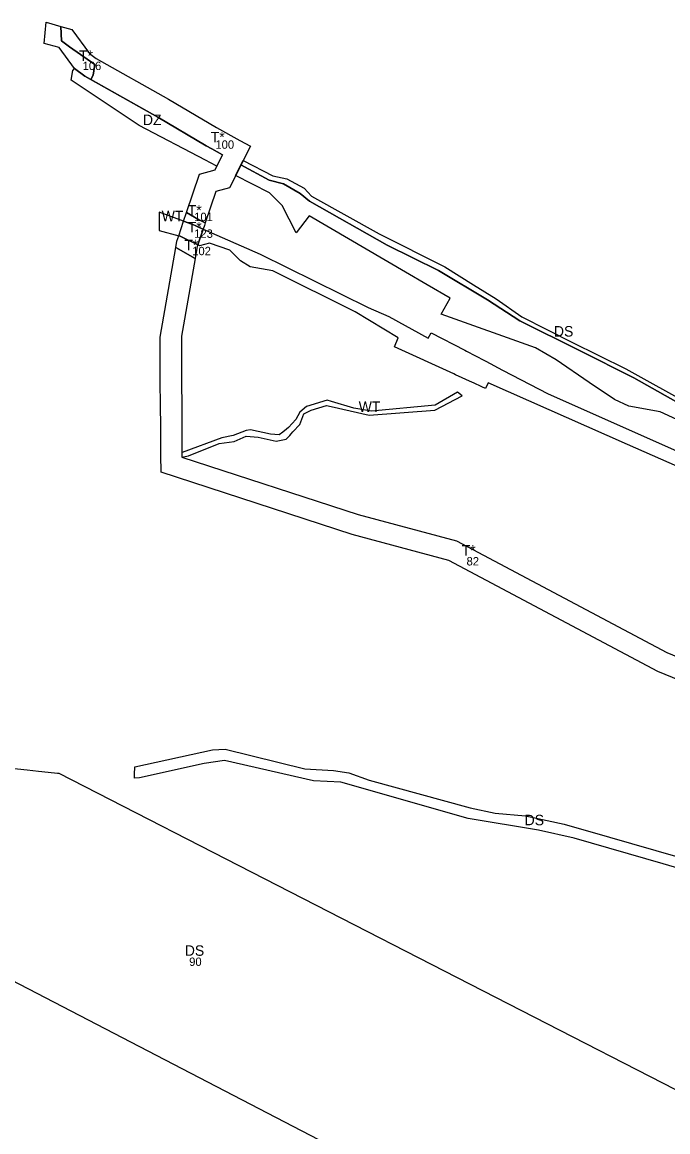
# Model space of a CAD drawing. Extents: x -521621 to -516769, y -1190068 to -1185078.
# Drawn here: x -520820 to -520203, y -1187500 to -1186440 of the extents above; entities that cross this region are included whole.
import ezdxf

# ---------------------------------------------------------------- set-up
doc = ezdxf.new("R2010")
doc.units = 0
for name, color, linetype in [('fpl_id', 7, 'Continuous'), ('v_infrastr_n', 7, 'Continuous'), ('v_infrastr_s', 7, 'Continuous'), ('voda_s', 7, 'Continuous')]:
    doc.layers.add(name, color=color, linetype=linetype)

msp = doc.modelspace()

# ---------------------------------------------------------------- linework, layer by layer
at = {"layer": 'v_infrastr_n'}
for points in [[(-520797.2, -1186439.6), (-520783, -1186443.6), (-520782.5, -1186457.5), (-520774.7, -1186463.1), (-520750.6, -1186480.1), (-520752.2, -1186490.3), (-520754.3, -1186494.4), (-520760.1, -1186491.2), (-520770, -1186483.8), (-520784.7, -1186463.9), (-520799.1, -1186459.9)], [(-520749.2, -1186474.3), (-520680.3, -1186513), (-520634.4, -1186540.3), (-520611.9, -1186552.6), (-520601.9, -1186558), (-520621.9, -1186597.7), (-520634.9, -1186601.2), (-520645.1, -1186631.2), (-520649.5, -1186629.2), (-520655.4, -1186625.8), (-520662.9, -1186621.4), (-520650.4, -1186584.7), (-520635.7, -1186580.7), (-520628.5, -1186566.3), (-520638.9, -1186560.6), (-520644.3, -1186557.7), (-520690.3, -1186530.3), (-520754.3, -1186494.4), (-520752.2, -1186490.3), (-520750.6, -1186480.1), (-520774.7, -1186463.1), (-520782.5, -1186457.5), (-520783, -1186443.6), (-520772.7, -1186446.5), (-520755.7, -1186469.5)], [(-520665.7, -1186629.7), (-520662.9, -1186621.4), (-520655.4, -1186625.8), (-520652.7, -1186627.4), (-520649.5, -1186629.2), (-520645.1, -1186631.2), (-520645.9, -1186633.8), (-520647.1, -1186637.2), (-520651.4, -1186635.3), (-520654.8, -1186633.8), (-520657.7, -1186632.5)], [(-520665.7, -1186629.7), (-520657.7, -1186632.5), (-520654.8, -1186633.8), (-520651.4, -1186635.3), (-520647.1, -1186637.2), (-520652.2, -1186652.3), (-520669.1, -1186644.1), (-520670.4, -1186643.7)], [(-520670.4, -1186643.7), (-520669.1, -1186644.1), (-520652.2, -1186652.3), (-520652.7, -1186653.6), (-520654.8, -1186665.4), (-520673.2, -1186654.8), (-520672.1, -1186648.7)]]:
    msp.add_lwpolyline(points, close=True, dxfattribs=at)
for points in [[(-520140.9, -1187089.3), (-520212.4, -1187059.9), (-520412.3, -1186953.8), (-520504.6, -1186929.1), (-520687.3, -1186869.5), (-520687.4, -1186853.1), (-520687.5, -1186835.5), (-520687.6, -1186830.6), (-520687.6, -1186824.5), (-520687.8, -1186807), (-520688, -1186781.6), (-520688.2, -1186740.5), (-520673.2, -1186654.8), (-520654.8, -1186665.4), (-520667.8, -1186739.5), (-520667.4, -1186850.6), (-520667.4, -1186855), (-520498.9, -1186909.9), (-520405, -1186935.1), (-520203.8, -1187041.8), (-520133.6, -1187070.6)], [(-520849, -1187150.2), (-520815.2, -1187153.9), (-520804.3, -1187155.1), (-520795.3, -1187156), (-520786.2, -1187157), (-520784.9, -1187157.2), (-520159, -1187477.9), (-520132.3, -1187491.8), (-520130, -1187493), (-520122.9, -1187496.1), (-520003.6, -1187488.8), (-519999.4, -1187501.1), (-519986.8, -1187542.4), (-519985.9, -1187549.9), (-519983.1, -1187579.6), (-519979.3, -1187615.3), (-519966.4, -1187650.5), (-519963.3, -1187659), (-520250.8, -1187655.6), (-520830.3, -1187354.9)]]:
    msp.add_lwpolyline(points, dxfattribs=at)
at = {"layer": 'v_infrastr_s'}
for points in [[(-520773.1, -1186494.9), (-520771.7, -1186485.7)], [(-520771.7, -1186485.7), (-520770, -1186483.8)], [(-520770, -1186483.8), (-520760.1, -1186491.2)], [(-520708.1, -1186538.4), (-520773.1, -1186494.9)], [(-520760.1, -1186491.2), (-520690.3, -1186530.3)], [(-520690.3, -1186530.3), (-520644.3, -1186557.7)], [(-520644.8, -1186571.5), (-520708.1, -1186538.4)], [(-520638.9, -1186560.6), (-520628.5, -1186566.3), (-520633.9, -1186577.1), (-520639.9, -1186574), (-520644.8, -1186571.5)], [(-520644.3, -1186557.7), (-520638.9, -1186560.6)], [(-520610.9, -1186575.9), (-520608.8, -1186571.6)], [(-520608.8, -1186571.6), (-520580.6, -1186586.5), (-520567, -1186589.1), (-520550.6, -1186598), (-520543.5, -1186605.9), (-520478.8, -1186641.8), (-520416.1, -1186673.3), (-520388.6, -1186690.5), (-520367.1, -1186703.9), (-520342.6, -1186721.1), (-520294.7, -1186745.2), (-520243.2, -1186770.8), (-520179.4, -1186806.2), (-520105.8, -1186840), (-520039.7, -1186870.3), (-520014.8, -1186870.1), (-520002.3, -1186868.2)], [(-520616.1, -1186586.1), (-520610.9, -1186575.9)], [(-520610.9, -1186575.9), (-520583.9, -1186590.5)], [(-519978.4, -1186874.2), (-519985.9, -1186873.1), (-520039.9, -1186874.8), (-520115.6, -1186839.8), (-520183, -1186808.9), (-520235.4, -1186779.2), (-520287.2, -1186753.1), (-520344.4, -1186724.9), (-520375.4, -1186704.9), (-520422, -1186676.8), (-520471.3, -1186652.6), (-520545.4, -1186610.7), (-520554.3, -1186603.4), (-520570.1, -1186594.1), (-520583.9, -1186590.5), (-520610.9, -1186575.9)], [(-520583.6, -1186602.6), (-520616.1, -1186586.1)], [(-520583.9, -1186590.5), (-520570.1, -1186594.1)], [(-520571.4, -1186614.8), (-520583.6, -1186602.6)], [(-520570.1, -1186594.1), (-520554.3, -1186603.4)], [(-520554.3, -1186603.4), (-520545.4, -1186610.7)], [(-520558.2, -1186640.9), (-520571.4, -1186614.8)], [(-520545.4, -1186610.7), (-520471.3, -1186652.6)], [(-520545.7, -1186624.6), (-520558.2, -1186640.9)], [(-520453.8, -1186678.4), (-520545.7, -1186624.6)], [(-520471.3, -1186652.6), (-520422, -1186676.8)], [(-520433, -1186690.6), (-520453.8, -1186678.4)], [(-520422, -1186676.8), (-520375.4, -1186704.9)], [(-520411.1, -1186703.4), (-520433, -1186690.6)], [(-520419.4, -1186718.5), (-520411.1, -1186703.4)], [(-520375.4, -1186704.9), (-520344.4, -1186724.9)], [(-520329.5, -1186750.8), (-520419.4, -1186718.5)], [(-520344.4, -1186724.9), (-520287.2, -1186753.1)], [(-520309.6, -1186762.1), (-520329.5, -1186750.8)], [(-520278, -1186783.8), (-520309.6, -1186762.1)], [(-520287.2, -1186753.1), (-520235.4, -1186779.2)], [(-520253.9, -1186800.1), (-520278, -1186783.8)], [(-520235.4, -1186779.2), (-520183, -1186808.9)], [(-520240.1, -1186806.4), (-520253.9, -1186800.1)], [(-520210.1, -1186811.7), (-520240.1, -1186806.4)], [(-520185.9, -1186822.9), (-520210.1, -1186811.7)], [(-520108.5, -1187272.6), (-520207.5, -1187243.6), (-520292.6, -1187219), (-520326.6, -1187211.6), (-520393.8, -1187200.4), (-520515.4, -1187165.5), (-520541.5, -1187164.4), (-520626.6, -1187144.9), (-520646.1, -1187147.8), (-520707.8, -1187161.6), (-520712.8, -1187161.7), (-520712.7, -1187159.3), (-520712.6, -1187156.9), (-520712.4, -1187152.2), (-520712.4, -1187150.9), (-520638, -1187134.6), (-520626.1, -1187134.1), (-520549.7, -1187152.9), (-520522.4, -1187154.5), (-520507.8, -1187156.8), (-520488.4, -1187163.7), (-520391.8, -1187190.3), (-520367.9, -1187195.1), (-520338.9, -1187197.9), (-520302, -1187205.9), (-520258.7, -1187218.1), (-520107.1, -1187261.9)]]:
    msp.add_lwpolyline(points, dxfattribs=at)
at = {"layer": 'voda_s'}
for points in [[(-520689, -1186638.6), (-520670.4, -1186643.7), (-520665.7, -1186629.7), (-520689.1, -1186621.2), (-520689.1, -1186623.1), (-520689.1, -1186624.6), (-520689, -1186631.8), (-520689, -1186638.6)], [(-520652.2, -1186652.3), (-520647.1, -1186637.2)], [(-520647.1, -1186637.2), (-520592.6, -1186661.2), (-520489.2, -1186712.1), (-520469.5, -1186720.7), (-520432, -1186741.4), (-520429, -1186736.3), (-520397, -1186753), (-520395.5, -1186753.8), (-520395.5, -1186753.8), (-520378, -1186762.9), (-520377, -1186763.5), (-520360.9, -1186771.9), (-520317.4, -1186794.6), (-520317.4, -1186794.6), (-520183.2, -1186854.2)], [(-519994.8, -1186969.5), (-520006.4, -1186946.6), (-520132.9, -1186890.9), (-520241.6, -1186842.9), (-520374.5, -1186784), (-520377.1, -1186789.5), (-520380.6, -1186787.9), (-520380.6, -1186787.9), (-520388.7, -1186784.2), (-520389.7, -1186783.7), (-520405.7, -1186776.4), (-520407.5, -1186775.6), (-520464.3, -1186749.8), (-520460.6, -1186741.1), (-520501.9, -1186716.2), (-520580.3, -1186677), (-520602.1, -1186673.3), (-520611.2, -1186667.5), (-520621.4, -1186657.5), (-520640.9, -1186650.8), (-520650.6, -1186653.1), (-520652.2, -1186652.3)], [(-520564.3, -1186834.4), (-520562.9, -1186832.9), (-520561.2, -1186831.1), (-520554.5, -1186823.9), (-520550.9, -1186813.6), (-520543.7, -1186810.2), (-520529.1, -1186805.7), (-520524.8, -1186806.7), (-520488.4, -1186814.9), (-520425.5, -1186810.4), (-520399.6, -1186796.7), (-520404, -1186793.2), (-520425.4, -1186805.4), (-520486.2, -1186811.2), (-520503.1, -1186808.4), (-520524.5, -1186802), (-520528.6, -1186800.8), (-520548.3, -1186806.6), (-520554.7, -1186812.2), (-520558.4, -1186819.3), (-520565.6, -1186826.8), (-520567.5, -1186828.5), (-520570.9, -1186831.2)], [(-520570.9, -1186831.2), (-520574.5, -1186833.9), (-520582.6, -1186833.3), (-520601.9, -1186829), (-520605.8, -1186829.6), (-520618.2, -1186834.4), (-520629.1, -1186836.6), (-520667, -1186850.8), (-520667.4, -1186850.6)], [(-520667.4, -1186855), (-520661, -1186854), (-520631.6, -1186842.2), (-520617.3, -1186840.2), (-520605.9, -1186835), (-520594.6, -1186836), (-520577.2, -1186839.9), (-520567.6, -1186837.9), (-520564.3, -1186834.4)], [(-520667.4, -1186850.6), (-520667.4, -1186855)]]:
    msp.add_lwpolyline(points, dxfattribs=at)

# ---------------------------------------------------------------- texts
at = {"layer": 'fpl_id'}
for s, p in [('106', (-520762.2, -1186485.3)), ('100', (-520635.3, -1186560.5)), ('101', (-520655.6, -1186629.6)), ('123', (-520655.6, -1186645.6)), ('102', (-520657.5, -1186662.2)), ('82', (-520395.3, -1186958.6)), ('90', (-520660.4, -1187341.2))]:
    msp.add_text(s, height=8, dxfattribs=at).set_placement(p)
at = {"layer": 'v_infrastr_n'}
for s, p in [('T*', (-520765.7, -1186476.6)), ('T*', (-520639.8, -1186554.4)), ('T*', (-520661.8, -1186624.3)), ('T*', (-520661.8, -1186640.4)), ('T*', (-520665, -1186657.4)), ('T*', (-520400, -1186949.2)), ('DS', (-520664.6, -1187331.5))]:
    msp.add_text(s, height=10, dxfattribs=at).set_placement(p)
at = {"layer": 'v_infrastr_s'}
for s, p in [('DZ', (-520704.6, -1186537.9)), ('DS', (-520311.8, -1186739.9)), ('DS', (-520339.8, -1187206.8))]:
    msp.add_text(s, height=10, dxfattribs=at).set_placement(p)
at = {"layer": 'voda_s'}
for p in [(-520686.7, -1186629.8), (-520498.4, -1186811.9)]:
    msp.add_text('WT', height=10, dxfattribs=at).set_placement(p)

doc.saveas('drawing.dxf')
